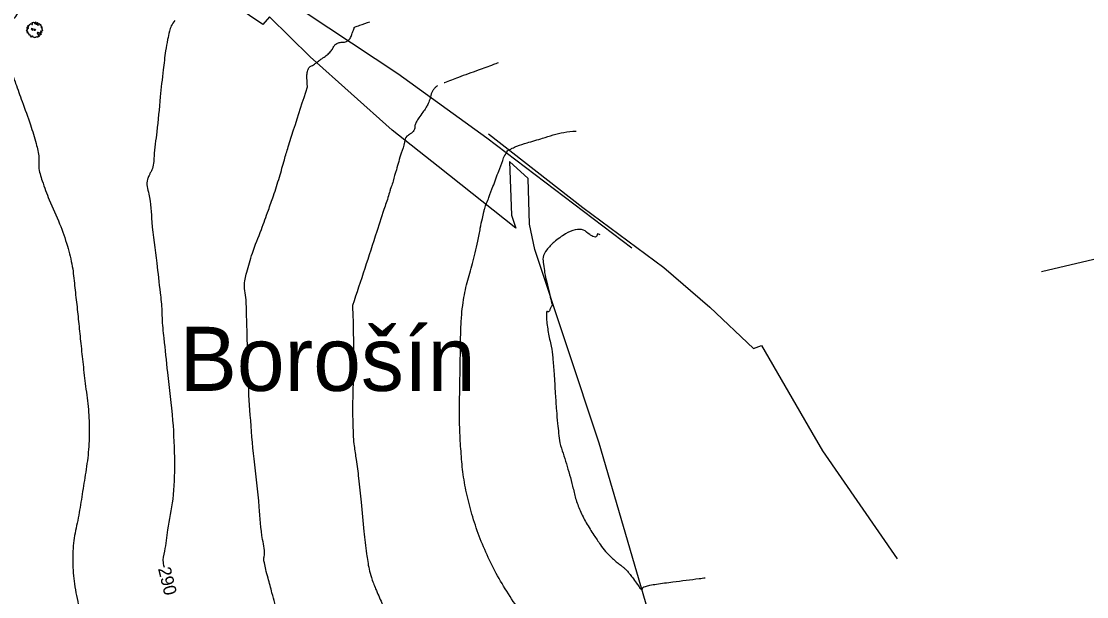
# Model space of a CAD drawing. Extents: x -478464 to -472469, y -1120963 to -1113785.
# Drawn here: x -475477.6 to -475145.7, y -1117051.2 to -1116871.8 of the extents above; entities that cross this region are included whole.
import ezdxf

# ---------------------------------------------------------------- set-up
doc = ezdxf.new("R2010")
doc.units = 0
for name, color, linetype in [('IP', 7, 'Continuous'), ('místní názvy', 7, 'Continuous'), ('ObPÚ', 7, 'Continuous'), ('plyn_ntl', 7, 'Continuous'), ('VAK_kanalizace', 7, 'Continuous'), ('Vrstevnice_hlavni', 7, 'Continuous'), ('Vrstevnice_popis', 7, 'Continuous'), ('Vrstevnice_vedlejsi', 7, 'Continuous')]:
    doc.layers.add(name, color=color, linetype=linetype)

msp = doc.modelspace()

# ---------------------------------------------------------------- linework, layer by layer
at = {"layer": 'IP'}
for points in [[(-475472.025, -1116872.452), (-475471.876, -1116872.566), (-475471.91, -1116872.695), (-475471.819, -1116872.871), (-475471.61, -1116872.966), (-475471.676, -1116872.795), (-475471.597, -1116872.772), (-475471.418, -1116872.965), (-475471.453, -1116872.954), (-475471.467, -1116873.249), (-475471.285, -1116873.27), (-475471.246, -1116873.399), (-475471.269, -1116873.517), (-475471.373, -1116873.542), (-475471.402, -1116873.613), (-475471.251, -1116873.766), (-475471.23, -1116873.642), (-475471.137, -1116873.784), (-475471.174, -1116873.918), (-475471.327, -1116873.969), (-475471.28, -1116874.063), (-475471.087, -1116874.021), (-475471.032, -1116874.114), (-475471.091, -1116874.25), (-475471.208, -1116874.364), (-475470.996, -1116874.492), (-475471, -1116874.615), (-475471.143, -1116874.744), (-475471.128, -1116874.899), (-475471.236, -1116874.923), (-475471.426, -1116874.832), (-475471.571, -1116874.88), (-475471.546, -1116875.039), (-475471.41, -1116875.123), (-475471.42, -1116875.039), (-475471.353, -1116875.002), (-475471.263, -1116874.984), (-475471.19, -1116875.137), (-475471.255, -1116875.225), (-475471.48, -1116875.195), (-475471.558, -1116875.145), (-475471.749, -1116875.172), (-475471.729, -1116875.18), (-475471.589, -1116875.429), (-475471.425, -1116875.45), (-475471.614, -1116875.573), (-475471.576, -1116875.694), (-475471.443, -1116875.75), (-475471.446, -1116875.847), (-475471.771, -1116875.864), (-475471.778, -1116876.023), (-475471.688, -1116876.101), (-475471.851, -1116876.194), (-475471.919, -1116876.094), (-475472.056, -1116876.125), (-475472.138, -1116876.249), (-475471.995, -1116876.397), (-475471.994, -1116876.484), (-475472.129, -1116876.464), (-475472.199, -1116876.417), (-475472.32, -1116876.423), (-475472.427, -1116876.506), (-475472.351, -1116876.665), (-475472.416, -1116876.725), (-475472.726, -1116876.692), (-475472.956, -1116876.57), (-475473.015, -1116876.841), (-475473.223, -1116876.786), (-475473.37, -1116876.802), (-475473.277, -1116876.971), (-475473.854, -1116876.671), (-475473.923, -1116876.509), (-475474.052, -1116876.503), (-475474.08, -1116876.428), (-475474.261, -1116876.425), (-475474.398, -1116876.452), (-475474.427, -1116876.608), (-475474.514, -1116876.678), (-475474.669, -1116876.598), (-475474.702, -1116876.314), (-475474.91, -1116876.113), (-475474.85, -1116876.001), (-475475.094, -1116876.046), (-475475.11, -1116875.801), (-475475.199, -1116875.774), (-475475.262, -1116875.549), (-475475.261, -1116875.496), (-475475.492, -1116875.434), (-475475.559, -1116875.472), (-475475.717, -1116875.413), (-475475.843, -1116875.333), (-475475.607, -1116875.123), (-475475.6, -1116874.956), (-475475.669, -1116874.814), (-475475.777, -1116874.849), (-475475.884, -1116874.976), (-475475.915, -1116874.738), (-475475.974, -1116874.491), (-475475.877, -1116874.404), (-475475.688, -1116874.445), (-475475.67, -1116874.321), (-475475.702, -1116874.17), (-475475.444, -1116874.037), (-475475.346, -1116873.923), (-475475.364, -1116873.829), (-475475.461, -1116873.906), (-475475.575, -1116873.906), (-475475.711, -1116873.99), (-475475.765, -1116873.815), (-475475.75, -1116873.563), (-475475.63, -1116873.514), (-475475.527, -1116873.635), (-475475.418, -1116873.675), (-475475.316, -1116873.464), (-475475.305, -1116873.429), (-475475.46, -1116873.427), (-475475.402, -1116873.309), (-475475.447, -1116873.236), (-475475.49, -1116873.105), (-475475.4, -1116873.003), (-475475.296, -1116873.047), (-475475.118, -1116873.03), (-475475.073, -1116872.892), (-475475.092, -1116872.806), (-475474.933, -1116872.718), (-475474.974, -1116872.625), (-475474.769, -1116872.668), (-475474.677, -1116872.616), (-475474.682, -1116872.512), (-475474.547, -1116872.467), (-475474.533, -1116872.537), (-475474.451, -1116872.53), (-475474.364, -1116872.556), (-475474.33, -1116872.595), (-475474.315, -1116872.661), (-475474.272, -1116872.721), (-475474.218, -1116872.763), (-475474.135, -1116872.739), (-475474.099, -1116872.639), (-475474.098, -1116872.419), (-475474.172, -1116872.248), (-475474.163, -1116872.144), (-475473.981, -1116872.174), (-475473.85, -1116872.13), (-475473.819, -1116872.052), (-475473.547, -1116872.113), (-475473.525, -1116872.181), (-475473.463, -1116872.276), (-475473.518, -1116872.474), (-475473.419, -1116872.481), (-475473.263, -1116872.394), (-475473.166, -1116872.552), (-475473, -1116872.661), (-475472.797, -1116872.619), (-475473.052, -1116872.395), (-475472.916, -1116872.384), (-475472.539, -1116872.56), (-475472.457, -1116872.426), (-475472.288, -1116872.326), (-475472.243, -1116872.346), (-475472.291, -1116872.449), (-475472.083, -1116872.653), (-475471.987, -1116872.61)], [(-475473.222, -1116872.161), (-475473.045, -1116872.273), (-475472.93, -1116872.288), (-475473.004, -1116872.133), (-475472.972, -1116872.109), (-475473.22, -1116872.074)], [(-475472.697, -1116872.194), (-475472.622, -1116872.273), (-475472.573, -1116872.235), (-475472.598, -1116872.2)], [(-475472.541, -1116872.74), (-475472.568, -1116872.897), (-475472.49, -1116873.047), (-475472.352, -1116872.996), (-475472.243, -1116872.892), (-475472.356, -1116872.755)], [(-475474.316, -1116874.181), (-475474.316, -1116874.323), (-475474.188, -1116874.525), (-475474.036, -1116874.428), (-475473.909, -1116874.254), (-475474.031, -1116873.994), (-475474.061, -1116874.169), (-475474.164, -1116874.152), (-475474.26, -1116874.082), (-475474.302, -1116874.051), (-475474.489, -1116874.074), (-475474.478, -1116874.168), (-475474.427, -1116874.244), (-475474.355, -1116874.214)], [(-475472.548, -1116875.264), (-475472.662, -1116875.592), (-475472.401, -1116875.833), (-475472.45, -1116875.886), (-475472.16, -1116875.893), (-475472.155, -1116875.674), (-475471.946, -1116875.452), (-475472.168, -1116875.243), (-475472.327, -1116875.412), (-475472.431, -1116875.314)]]:
    msp.add_lwpolyline(points, close=True, dxfattribs=at)
msp.add_circle((-475473.454, -1116874.42), 0.247, dxfattribs=at)
at = {"layer": 'ObPÚ'}
msp.add_lwpolyline([(-475278.26, -1117069.58), (-475297.51, -1117003.35), (-475317.58, -1116942.95), (-475319.3, -1116935.03), (-475319.62, -1116920.77), (-475325.44, -1116915.53), (-475324.87, -1116932.22), (-475323.56, -1116936.27), (-475347.68, -1116917.03), (-475362.02, -1116905.75), (-475387.57, -1116882.83), (-475400.22, -1116870.41), (-475402.3, -1116872.82), (-475415.08, -1116864.04)], dxfattribs=at)
at = {"layer": 'plyn_ntl'}
msp.add_line((-475159.739, -1116949.817), (-475085.711, -1116932.42), dxfattribs=at)
msp.add_lwpolyline([(-475332.027, -1116906.834), (-475302.68, -1116929.803), (-475277.372, -1116948.522), (-475263.116, -1116960.887), (-475249.441, -1116973.786), (-475246.966, -1116972.922), (-475231.302, -1117000), (-475227.984, -1117005.735), (-475204.731, -1117039.46)], dxfattribs=at)
at = {"layer": 'VAK_kanalizace'}
for p, q in [((-475360.25, -1116888.13), (-475409.68, -1116855.4)), ((-475332.51, -1116908.19), (-475360.25, -1116888.13)), ((-475287.339, -1116942.523), (-475332.51, -1116908.19))]:
    msp.add_line(p, q, dxfattribs=at)
at = {"layer": 'Vrstevnice_hlavni'}
msp.add_spline([(-475429.795, -1116871.525), (-475430.862, -1116873.169), (-475431.421, -1116874.879), (-475432.005, -1116877.476), (-475432.616, -1116880.961), (-475433.38, -1116886.923), (-475434.299, -1116895.361), (-475435.371, -1116906.276), (-475436.245, -1116913.865), (-475436.92, -1116918.128), (-475437.396, -1116919.064), (-475437.778, -1116919.86), (-475438.065, -1116920.516), (-475438.259, -1116921.032), (-475437.875, -1116925.648), (-475436.914, -1116934.365), (-475435.376, -1116947.183), (-475434.337, -1116956.426), (-475433.796, -1116962.096), (-475433.753, -1116964.193), (-475433.181, -1116970.579), (-475432.078, -1116981.255), (-475430.445, -1116996.221), (-475429.89, -1117009.4), (-475430.411, -1117020.792), (-475432.01, -1117030.396), (-475433.018, -1117037.022), (-475433.434, -1117040.669), (-475433.084, -1117042.006)], degree=3, dxfattribs=at)
at = {"layer": 'Vrstevnice_vedlejsi'}
for points in [[(-475414.69, -1116829.479), (-475424.402, -1116830.078), (-475431.9, -1116830.525), (-475435.845, -1116830.736), (-475436.238, -1116830.711), (-475436.749, -1116831.021), (-475437.378, -1116831.667), (-475438.124, -1116832.648), (-475438.645, -1116833.401), (-475438.94, -1116833.925), (-475439.01, -1116834.221), (-475439.622, -1116834.381), (-475440.779, -1116834.405), (-475442.478, -1116834.293), (-475444.075, -1116834.18), (-475445.57, -1116834.066), (-475446.963, -1116833.951), (-475448.293, -1116834.253), (-475449.561, -1116834.972), (-475450.766, -1116836.108), (-475452.218, -1116837.401), (-475453.917, -1116838.851), (-475455.864, -1116840.458), (-475457.735, -1116841.921), (-475459.532, -1116843.24), (-475461.254, -1116844.414), (-475464.293, -1116848.071), (-475468.651, -1116854.212), (-475474.325, -1116862.835), (-475478.494, -1116868.885), (-475481.158, -1116872.36), (-475483.473, -1116874.163)], [(-475388.408, -1116892.2), (-475388.578, -1116888.463), (-475388.343, -1116887.037), (-475387.788, -1116886.054), (-475386.912, -1116885.513), (-475386.256, -1116885.093), (-475385.822, -1116884.792), (-475385.609, -1116884.612), (-475384.995, -1116884.161), (-475383.982, -1116883.441), (-475382.569, -1116882.451), (-475381.454, -1116881.45), (-475380.637, -1116880.436), (-475380.119, -1116879.411), (-475379.321, -1116878.71), (-475378.243, -1116878.333), (-475376.886, -1116878.28), (-475375.807, -1116877.79), (-475375.005, -1116876.861), (-475374.48, -1116875.495), (-475374.11, -1116874.521), (-475373.895, -1116873.94), (-475373.834, -1116873.752), (-475373.523, -1116873.533), (-475372.963, -1116873.283), (-475372.153, -1116873.002), (-475368.958, -1116871.897)], [(-475483.473, -1116874.163), (-475483.927, -1116878.919), (-475483.861, -1116880.7), (-475483.504, -1116881.882), (-475482.855, -1116882.468), (-475482.177, -1116883.562), (-475481.47, -1116885.165), (-475480.735, -1116887.276), (-475479.367, -1116891.133), (-475477.366, -1116896.735), (-475474.732, -1116904.082), (-475472.982, -1116909.932), (-475472.116, -1116914.286), (-475472.134, -1116917.143), (-475471.062, -1116921.536), (-475468.901, -1116927.466), (-475465.649, -1116934.931), (-475463.246, -1116941.864), (-475461.693, -1116948.264), (-475460.988, -1116954.132), (-475460.314, -1116960.093), (-475459.669, -1116966.146), (-475459.053, -1116972.292), (-475458.349, -1116978.785), (-475457.558, -1116985.625), (-475456.678, -1116992.812), (-475456.427, -1116999.958), (-475456.805, -1117007.06), (-475457.812, -1117014.12), (-475458.884, -1117020.919), (-475460.021, -1117027.456), (-475461.222, -1117033.732), (-475461.561, -1117040.33), (-475461.038, -1117047.251), (-475459.652, -1117054.494), (-475458.614, -1117061.46), (-475457.925, -1117068.148), (-475457.583, -1117074.558), (-475456.531, -1117079.949), (-475454.766, -1117084.319), (-475452.29, -1117087.668), (-475449.549, -1117092.735), (-475446.543, -1117099.519), (-475443.271, -1117108.021), (-475440.931, -1117114.066), (-475439.522, -1117117.657), (-475439.045, -1117118.792), (-475438.698, -1117119.719), (-475438.482, -1117120.438), (-475438.396, -1117120.948), (-475438.037, -1117125.501), (-475437.405, -1117134.099), (-475436.498, -1117146.74), (-475434.664, -1117156.956), (-475431.901, -1117164.748), (-475428.209, -1117170.115), (-475424.281, -1117176.417), (-475420.117, -1117183.655), (-475415.717, -1117191.827), (-475411.526, -1117198.054), (-475407.544, -1117202.335), (-475403.772, -1117204.67), (-475398.49, -1117207.23), (-475391.697, -1117210.014), (-475383.394, -1117213.023), (-475376.171, -1117216.013), (-475370.027, -1117218.985), (-475364.962, -1117221.938), (-475359.223, -1117223.532), (-475352.81, -1117223.769), (-475345.723, -1117222.646), (-475338.939, -1117221.608), (-475332.458, -1117220.652), (-475326.28, -1117219.78), (-475319.199, -1117218.553), (-475311.214, -1117216.973), (-475302.325, -1117215.038), (-475294.906, -1117212.887), (-475288.957, -1117210.518), (-475284.479, -1117207.932), (-475281.122, -1117205.985), (-475278.886, -1117204.678), (-475277.773, -1117204.009), (-475275.916, -1117203.193), (-475273.318, -1117202.227), (-475269.976, -1117201.114), (-475266.068, -1117199.182), (-475261.591, -1117196.432), (-475256.547, -1117192.863), (-475251.894, -1117189.887), (-475247.633, -1117187.504), (-475243.763, -1117185.713), (-475239.95, -1117183.011), (-475236.193, -1117179.397), (-475232.493, -1117174.871), (-475228.427, -1117171.086), (-475223.996, -1117168.041)], [(-475546.801, -1116880), (-475537.676, -1116888.742), (-475533.177, -1116892.938), (-475528.742, -1116896.961), (-475524.371, -1116900.808), (-475520.702, -1116904.312), (-475517.736, -1116907.472), (-475515.473, -1116910.287), (-475513.66, -1116912.425), (-475512.297, -1116913.886), (-475511.384, -1116914.668), (-475510.565, -1116916.318), (-475509.839, -1116918.836), (-475509.207, -1116922.221), (-475508.369, -1116925.736), (-475507.326, -1116929.379), (-475506.079, -1116933.151), (-475505.195, -1116935.849), (-475504.673, -1116937.472), (-475504.514, -1116938.021), (-475504.049, -1116938.551), (-475503.277, -1116939.062), (-475502.199, -1116939.555), (-475501.244, -1116940.19), (-475500.412, -1116940.967), (-475499.704, -1116941.885), (-475498.862, -1116943.219), (-475497.885, -1116944.968), (-475496.774, -1116947.132), (-475495.06, -1116950.073), (-475492.744, -1116953.792), (-475489.824, -1116958.289), (-475487.754, -1116961.617), (-475486.534, -1116963.779), (-475486.164, -1116964.772), (-475485.578, -1116969.025), (-475484.777, -1116976.536), (-475483.762, -1116987.305), (-475483.099, -1116994.584), (-475482.79, -1116998.37), (-475482.835, -1116998.665), (-475482.937, -1116999.023), (-475483.098, -1116999.444), (-475483.316, -1116999.928), (-475483.539, -1117000.507), (-475483.765, -1117001.179), (-475483.995, -1117001.947), (-475484.859, -1117005.458), (-475486.356, -1117011.714), (-475488.487, -1117020.713), (-475490.031, -1117027.652), (-475490.989, -1117032.53), (-475491.361, -1117035.346), (-475491.512, -1117037.985), (-475491.442, -1117040.446), (-475491.152, -1117042.73), (-475490.802, -1117044.507), (-475490.391, -1117045.777), (-475489.92, -1117046.542), (-475489.45, -1117049.972), (-475488.982, -1117056.067), (-475488.516, -1117064.827), (-475488.087, -1117071.069), (-475487.695, -1117074.792), (-475487.34, -1117075.996), (-475487.005, -1117077.178), (-475486.691, -1117078.338), (-475486.397, -1117079.477), (-475486.144, -1117080.687), (-475485.93, -1117081.968), (-475485.757, -1117083.32), (-475485.828, -1117084.635), (-475486.143, -1117085.912), (-475486.701, -1117087.153), (-475487.191, -1117088.19), (-475487.612, -1117089.023), (-475487.963, -1117089.652), (-475488.153, -1117090.264), (-475488.181, -1117090.86), (-475488.048, -1117091.439), (-475487.898, -1117092.054), (-475487.733, -1117092.705), (-475487.551, -1117093.394), (-475486.121, -1117094.779), (-475483.444, -1117096.86), (-475479.52, -1117099.639), (-475476.116, -1117102.556), (-475473.233, -1117105.613), (-475470.87, -1117108.809), (-475469.016, -1117111.665), (-475467.67, -1117114.182), (-475466.832, -1117116.36), (-475466.308, -1117119.273), (-475466.097, -1117122.923), (-475466.201, -1117127.308), (-475466.496, -1117131.344), (-475466.983, -1117135.032)], [(-475328.986, -1116884.687), (-475330.497, -1116885.289), (-475335.221, -1116887.062), (-475341.419, -1116889.273), (-475345.779, -1116890.973), (-475345.865, -1116891.007)], [(-475230.45, -1117129.665), (-475231.154, -1117130.236), (-475232.604, -1117131.14), (-475234.799, -1117132.377), (-475237.739, -1117133.949), (-475240.095, -1117135.166), (-475241.867, -1117136.029), (-475243.053, -1117136.538), (-475244.117, -1117137.032), (-475245.059, -1117137.512), (-475245.879, -1117137.977), (-475246.667, -1117138.415), (-475247.423, -1117138.827), (-475248.148, -1117139.213), (-475249.147, -1117139.513), (-475250.419, -1117139.728), (-475251.966, -1117139.857), (-475253.868, -1117140.287), (-475256.127, -1117141.019), (-475258.743, -1117142.053), (-475260.976, -1117142.929), (-475262.826, -1117143.649), (-475264.294, -1117144.212), (-475265.569, -1117144.802), (-475266.65, -1117145.422), (-475267.538, -1117146.069), (-475268.319, -1117146.603), (-475268.995, -1117147.022), (-475269.564, -1117147.327), (-475270.101, -1117147.563), (-475270.605, -1117147.731), (-475271.077, -1117147.83), (-475272.479, -1117147.419), (-475274.813, -1117146.498), (-475278.078, -1117145.068), (-475283.398, -1117144.708), (-475290.773, -1117145.419), (-475300.204, -1117147.201), (-475307.579, -1117148.515), (-475312.899, -1117149.364), (-475316.165, -1117149.745), (-475320.689, -1117148.813), (-475326.472, -1117146.566), (-475333.514, -1117143.005), (-475340.37, -1117140.425), (-475347.038, -1117138.826), (-475353.519, -1117138.209), (-475358.924, -1117136.773), (-475363.253, -1117134.517), (-475366.507, -1117131.441), (-475368.893, -1117128.401), (-475370.412, -1117125.396), (-475371.065, -1117122.428), (-475372.479, -1117118.228), (-475374.656, -1117112.795), (-475377.594, -1117106.131), (-475380.603, -1117099.526), (-475383.684, -1117092.978), (-475386.835, -1117086.489), (-475389.299, -1117081.414), (-475391.078, -1117077.754), (-475392.169, -1117075.508), (-475393.646, -1117071.217), (-475395.508, -1117064.881), (-475397.754, -1117056.501), (-475399.487, -1117050.011), (-475400.708, -1117045.414), (-475401.417, -1117042.707), (-475401.855, -1117040.7), (-475402.024, -1117039.393), (-475401.923, -1117038.785), (-475402.4, -1117033.392), (-475403.455, -1117023.212), (-475405.088, -1117008.246), (-475406.251, -1116994.57), (-475406.944, -1116982.186), (-475407.168, -1116971.093), (-475407.429, -1116962.764), (-475407.728, -1116957.2), (-475408.064, -1116954.4), (-475407.354, -1116950.045), (-475405.6, -1116944.134), (-475402.8, -1116936.668), (-475400.611, -1116930.699), (-475399.034, -1116926.23), (-475398.067, -1116923.259), (-475397.178, -1116920.387), (-475396.366, -1116917.617), (-475395.631, -1116914.946), (-475394.42, -1116910.935), (-475392.733, -1116905.584), (-475388.408, -1116892.2)], [(-475347.871, -1116891.916), (-475348.301, -1116892.162), (-475348.983, -1116892.841), (-475349.511, -1116893.598), (-475349.883, -1116894.436), (-475350.099, -1116895.353), (-475350.348, -1116896.207), (-475350.631, -1116896.998), (-475350.948, -1116897.726), (-475351.567, -1116898.776), (-475352.487, -1116900.149), (-475353.709, -1116901.845), (-475354.54, -1116903.235), (-475354.98, -1116904.319), (-475355.029, -1116905.098), (-475355.283, -1116905.783), (-475355.744, -1116906.374), (-475356.41, -1116906.872), (-475356.927, -1116907.248), (-475357.294, -1116907.5), (-475357.512, -1116907.63), (-475358.159, -1116909.437), (-475359.235, -1116912.921), (-475360.74, -1116918.083), (-475361.773, -1116921.583), (-475362.334, -1116923.421), (-475362.423, -1116923.597), (-475362.545, -1116923.943), (-475362.7, -1116924.457), (-475362.887, -1116925.141), (-475364.27, -1116929.441), (-475366.847, -1116937.355), (-475374.392, -1116960.415)], [(-475338.726, -1116953.226), (-475337.027, -1116947.322), (-475336.193, -1116944.004), (-475335.375, -1116940.322), (-475334.574, -1116936.274), (-475333.943, -1116933.226), (-475333.484, -1116931.176), (-475333.197, -1116930.125), (-475332.956, -1116929.328), (-475332.762, -1116928.784), (-475332.614, -1116928.494), (-475331.906, -1116926.679), (-475330.638, -1116923.34), (-475328.808, -1116918.477), (-475327.565, -1116915.206), (-475326.908, -1116913.528), (-475326.837, -1116913.442), (-475326.741, -1116913.299), (-475326.62, -1116913.1), (-475326.474, -1116912.844), (-475326.349, -1116912.608), (-475326.246, -1116912.393), (-475326.164, -1116912.198), (-475325.627, -1116911.852), (-475324.635, -1116911.355), (-475323.188, -1116910.708), (-475320.027, -1116909.667), (-475315.154, -1116908.232), (-475308.568, -1116906.403), (-475304.756, -1116906.007)], [(-475297.192, -1116938.412), (-475298.122, -1116938.143), (-475298.328, -1116938.926), (-475299.122, -1116938.977), (-475300.506, -1116938.296), (-475302.478, -1116936.883), (-475304.977, -1116936.801), (-475308.002, -1116938.049), (-475311.554, -1116940.626), (-475313.888, -1116943.068), (-475315.003, -1116945.373), (-475314.899, -1116947.541), (-475314.53, -1116950.142), (-475313.897, -1116953.173), (-475312.999, -1116956.636), (-475312.471, -1116959.071), (-475312.312, -1116960.477), (-475312.524, -1116960.855), (-475312.712, -1116961.24), (-475312.876, -1116961.632), (-475313.017, -1116962.031), (-475313.227, -1116962.272), (-475313.504, -1116962.354), (-475313.849, -1116962.279), (-475314.002, -1116962.956), (-475313.963, -1116964.387), (-475313.732, -1116966.572), (-475313.408, -1116968.758), (-475312.993, -1116970.944)], [(-475275.887, -1117084.879), (-475276.004, -1117084.841), (-475276.13, -1117084.799), (-475276.265, -1117084.754), (-475276.409, -1117084.705), (-475276.715, -1117084.783), (-475277.182, -1117084.99), (-475277.811, -1117085.325), (-475278.469, -1117085.803), (-475279.155, -1117086.423), (-475279.871, -1117087.185), (-475281.707, -1117087.011), (-475284.662, -1117085.901), (-475288.738, -1117083.854), (-475293.188, -1117081.647), (-475298.012, -1117079.278), (-475303.21, -1117076.749), (-475307.014, -1117074.748), (-475309.423, -1117073.276), (-475310.438, -1117072.332), (-475312.101, -1117070.33), (-475314.41, -1117067.269), (-475317.366, -1117063.149), (-475320.664, -1117058.288), (-475324.303, -1117052.686), (-475328.284, -1117046.343), (-475331.715, -1117039.84), (-475334.595, -1117033.177), (-475336.926, -1117026.353), (-475338.693, -1117019.667), (-475339.896, -1117013.118), (-475340.534, -1117006.707), (-475340.926, -1117000.108), (-475341.071, -1116993.322), (-475340.97, -1116986.349), (-475340.866, -1116979.834), (-475340.759, -1116973.776), (-475340.649, -1116968.178), (-475340.374, -1116963.406), (-475339.935, -1116959.461), (-475338.726, -1116953.226)], [(-475374.392, -1116960.415), (-475374.141, -1116969.663), (-475374.116, -1116975.603), (-475374.191, -1116982.858), (-475374.367, -1116991.429), (-475374.268, -1116998.543), (-475373.896, -1117004.201), (-475373.25, -1117008.402), (-475372.522, -1117014.247), (-475371.713, -1117021.736), (-475370.822, -1117030.868), (-475369.995, -1117037.826), (-475369.232, -1117042.611), (-475368.532, -1117045.221), (-475367.195, -1117048.752), (-475365.221, -1117053.203), (-475362.611, -1117058.574), (-475359.842, -1117063.926), (-475356.915, -1117069.257), (-475353.83, -1117074.568), (-475350.539, -1117080.236), (-475347.042, -1117086.261), (-475343.338, -1117092.642), (-475338.483, -1117098.62), (-475332.476, -1117104.196), (-475325.316, -1117109.368), (-475319.829, -1117113.173), (-475316.013, -1117115.611), (-475313.87, -1117116.681), (-475309.204, -1117117.223), (-475302.017, -1117117.236), (-475292.308, -1117116.72), (-475284.802, -1117116.975), (-475279.501, -1117118), (-475276.404, -1117119.796), (-475274.235, -1117121.046), (-475272.994, -1117121.75), (-475272.681, -1117121.908), (-475272.444, -1117121.994), (-475272.282, -1117122.005), (-475272.195, -1117121.944), (-475272.023, -1117121.864), (-475271.765, -1117121.767), (-475271.422, -1117121.652), (-475269.297, -1117120.841), (-475265.39, -1117119.334), (-475259.701, -1117117.133), (-475254.921, -1117114.586), (-475251.05, -1117111.694), (-475248.087, -1117108.458), (-475247.618, -1117107.969)], [(-475312.993, -1116970.944), (-475312.486, -1116973.131), (-475312.022, -1116976.69), (-475311.603, -1116981.62), (-475311.227, -1116987.923), (-475310.862, -1116993.129), (-475310.509, -1116997.238), (-475309.823, -1117003.262)], [(-475309.823, -1117003.262), (-475307.771, -1117009.748), (-475306.778, -1117013.174), (-475305.817, -1117016.784), (-475304.888, -1117020.578), (-475303.472, -1117024.382), (-475301.566, -1117028.197), (-475299.173, -1117032.021), (-475297.162, -1117034.998), (-475295.536, -1117037.125), (-475294.293, -1117038.405), (-475293.097, -1117039.545), (-475291.947, -1117040.546), (-475290.844, -1117041.408), (-475289.965, -1117042.12), (-475289.311, -1117042.684), (-475288.881, -1117043.099), (-475288.178, -1117043.956), (-475287.202, -1117045.255), (-475285.952, -1117046.995), (-475285.085, -1117048.167), (-475284.6, -1117048.771), (-475284.499, -1117048.806), (-475284.409, -1117048.854), (-475284.331, -1117048.916), (-475284.265, -1117048.992), (-475284.175, -1117048.928), (-475284.063, -1117048.723), (-475283.928, -1117048.377), (-475283.162, -1117048.025), (-475281.765, -1117047.666), (-475279.737, -1117047.3), (-475274.598, -1117046.595), (-475266.348, -1117045.552), (-475264.531, -1117045.328)]]:
    msp.add_spline(points, degree=3, dxfattribs=at)

# ---------------------------------------------------------------- texts
at = {"layer": 'místní názvy'}
msp.add_text('Borošín', height=20, rotation=359.99999, dxfattribs=at).set_placement((-475428.264, -1116987.037))
at = {"layer": 'Vrstevnice_popis'}
msp.add_text(' 290 ', height=4, rotation=283.72812, dxfattribs=at).set_placement((-475435.388, -1117041.002))

doc.saveas('drawing.dxf')
